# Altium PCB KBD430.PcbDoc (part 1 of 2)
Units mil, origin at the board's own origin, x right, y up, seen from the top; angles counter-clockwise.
Board outline 5000 x 5500 mil, 4 copper layers (Top Layer, Ground Plane, Power Plane, Bottom Layer), stack 90 mil thick; 72 components, 94 nets, 353 pads, 293 vias.
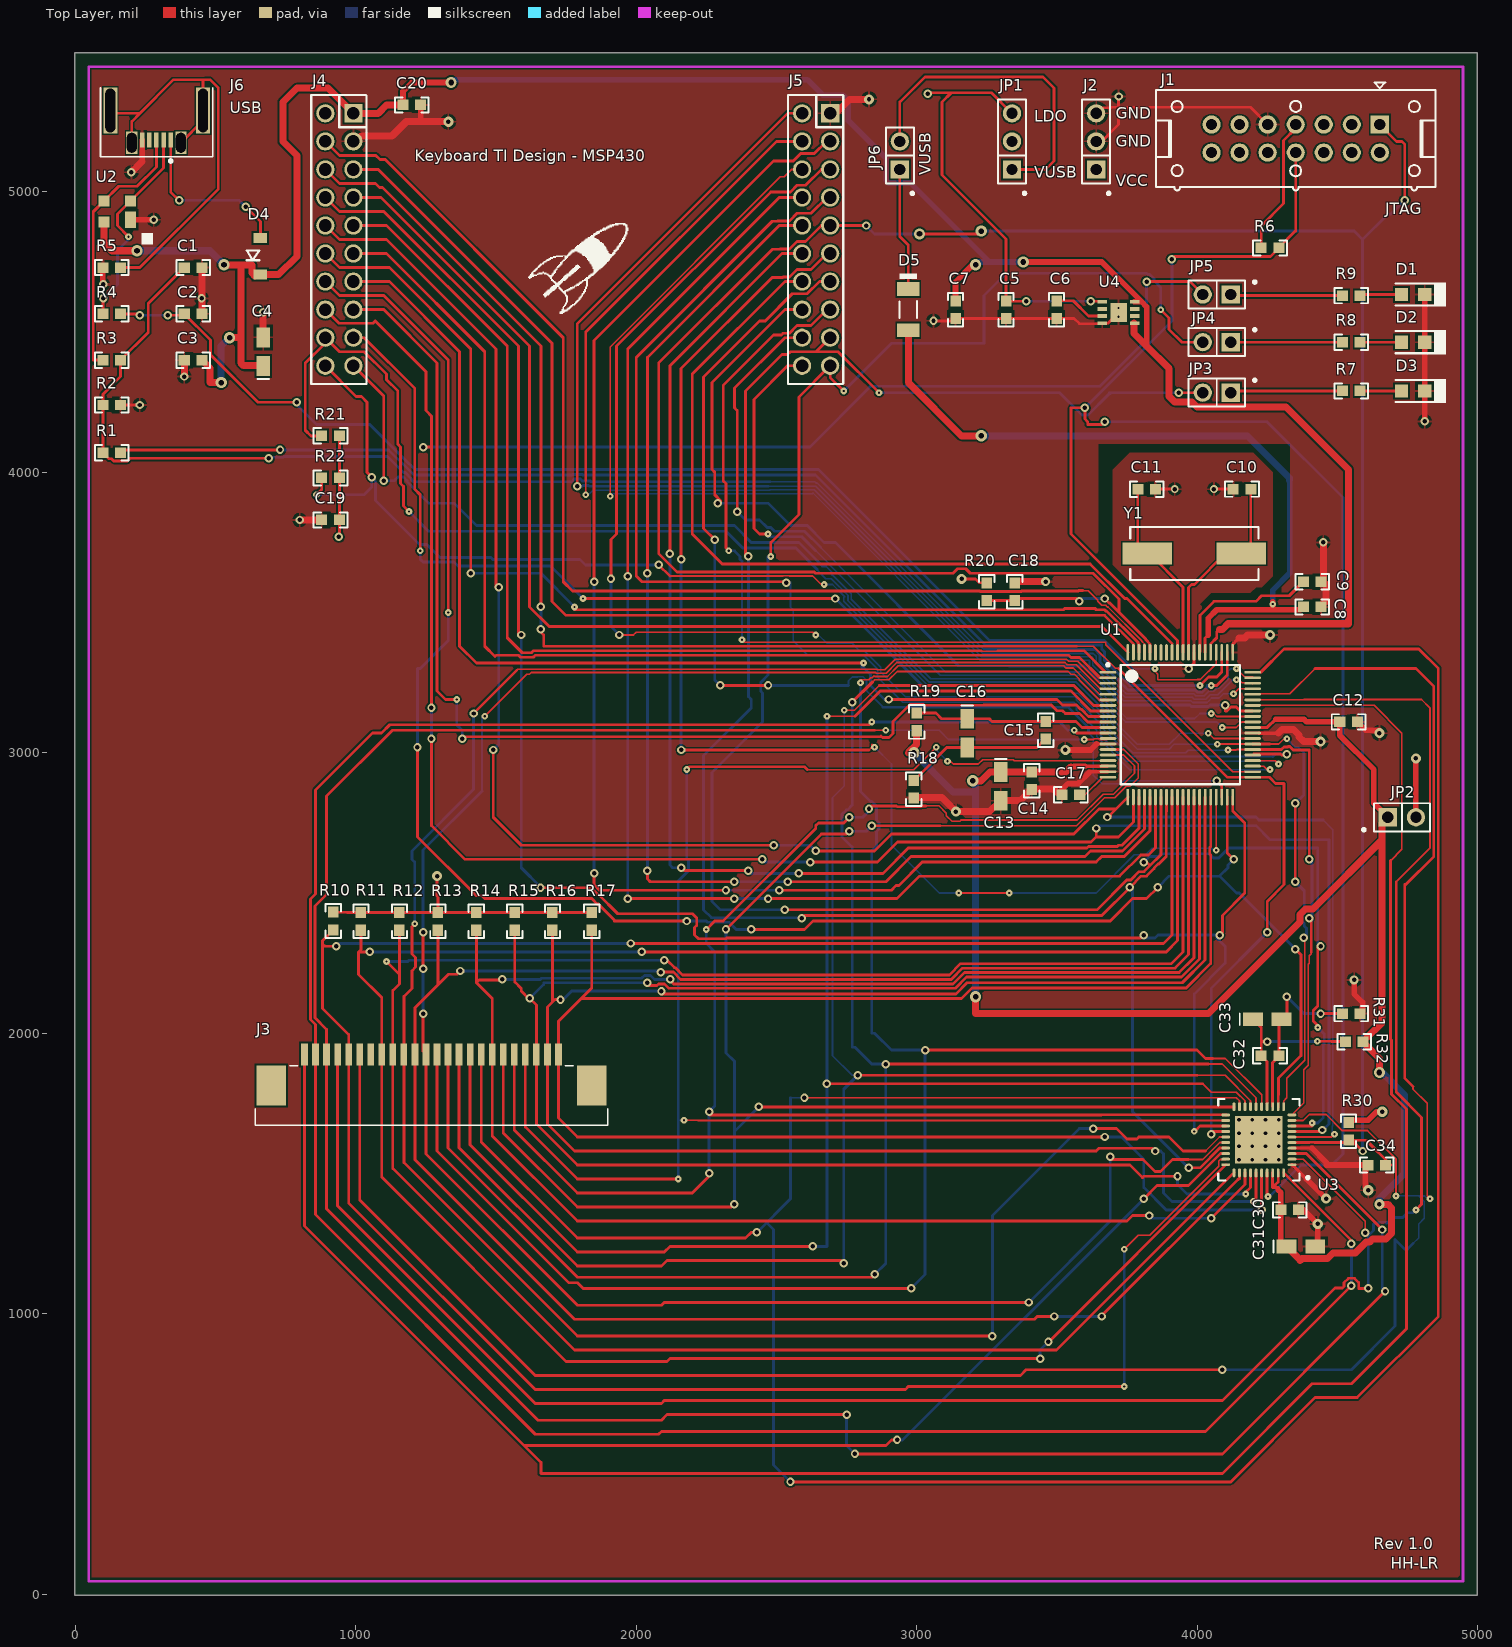
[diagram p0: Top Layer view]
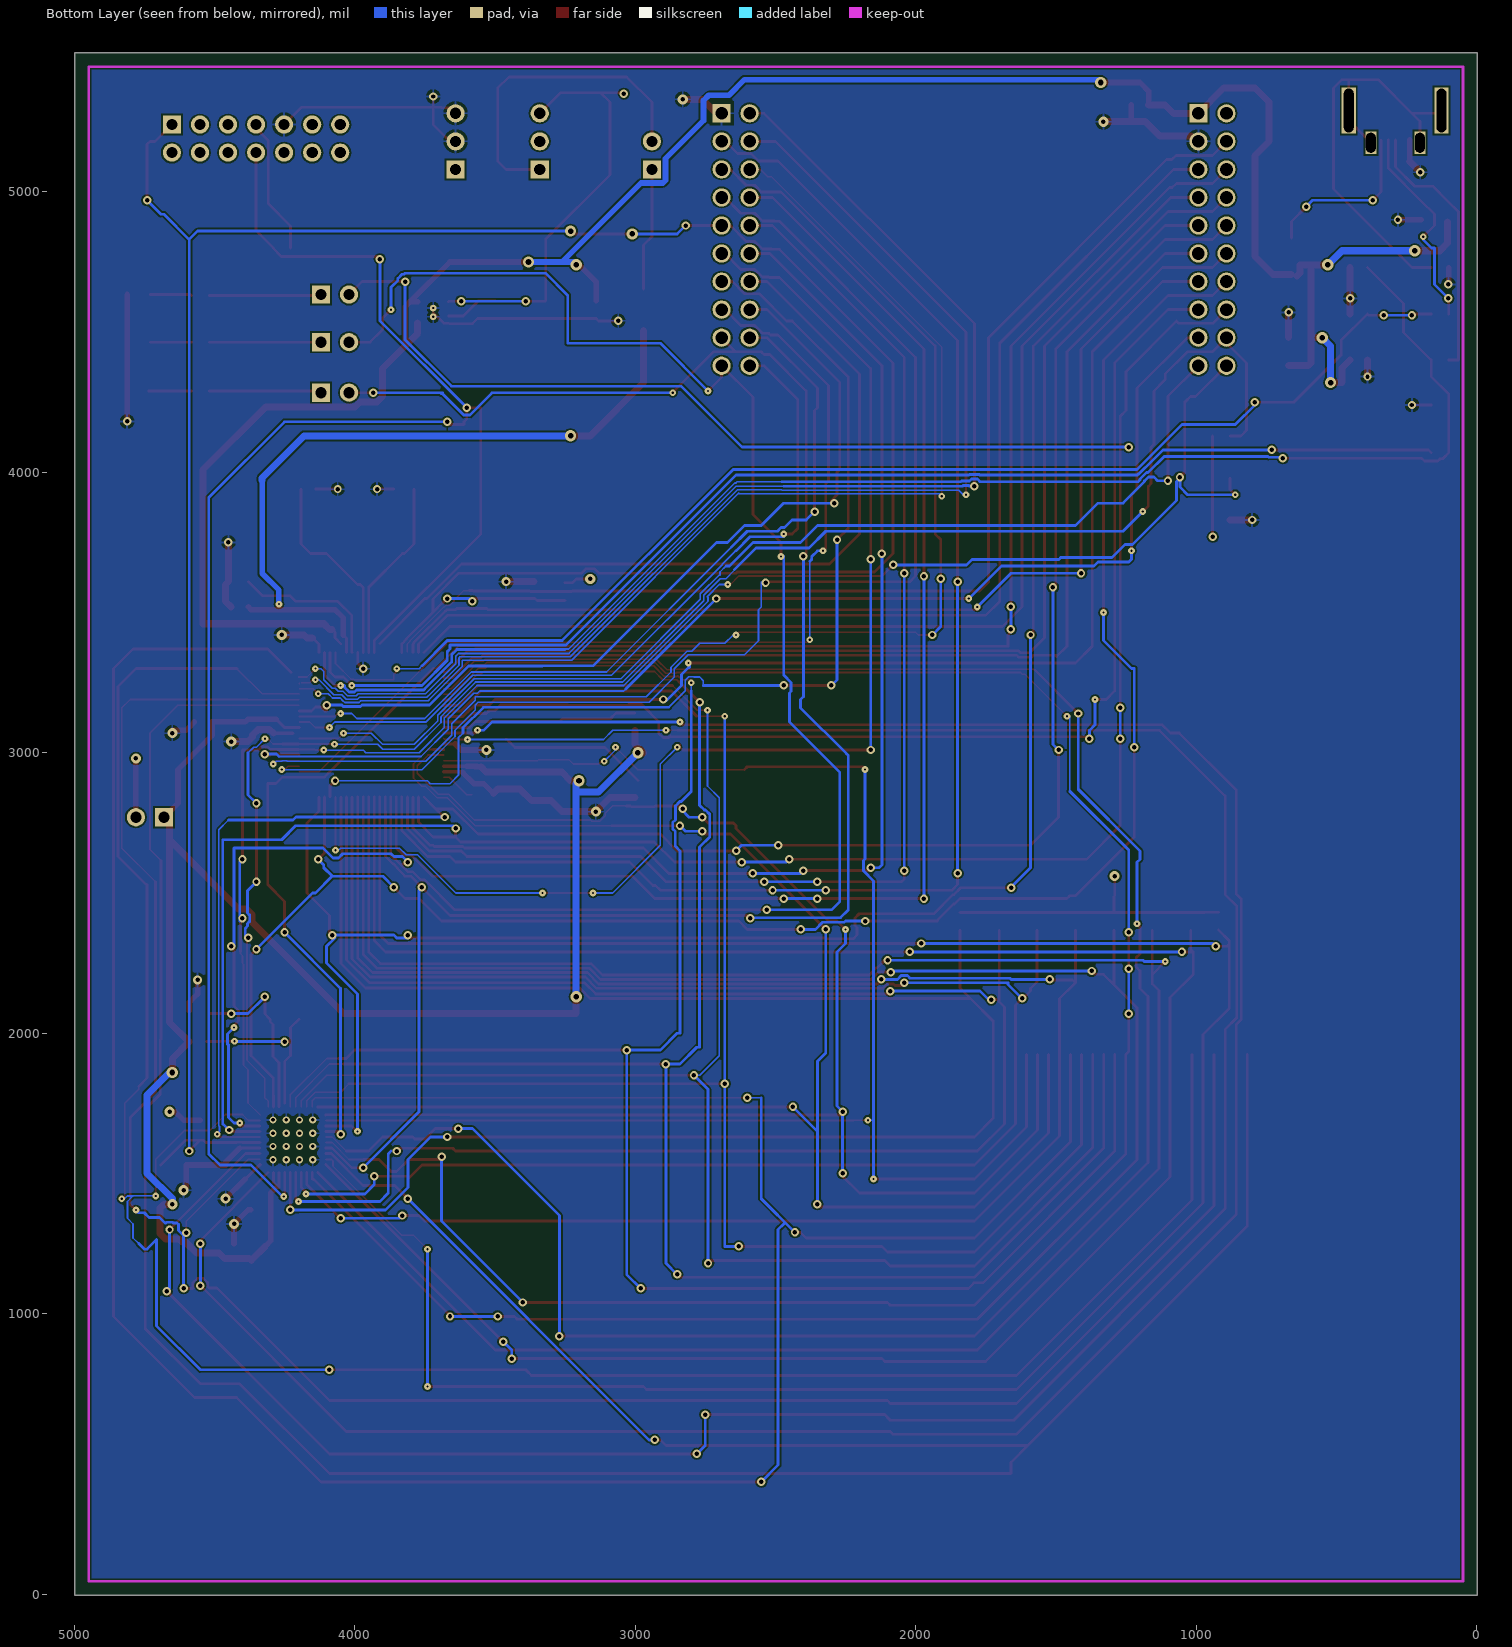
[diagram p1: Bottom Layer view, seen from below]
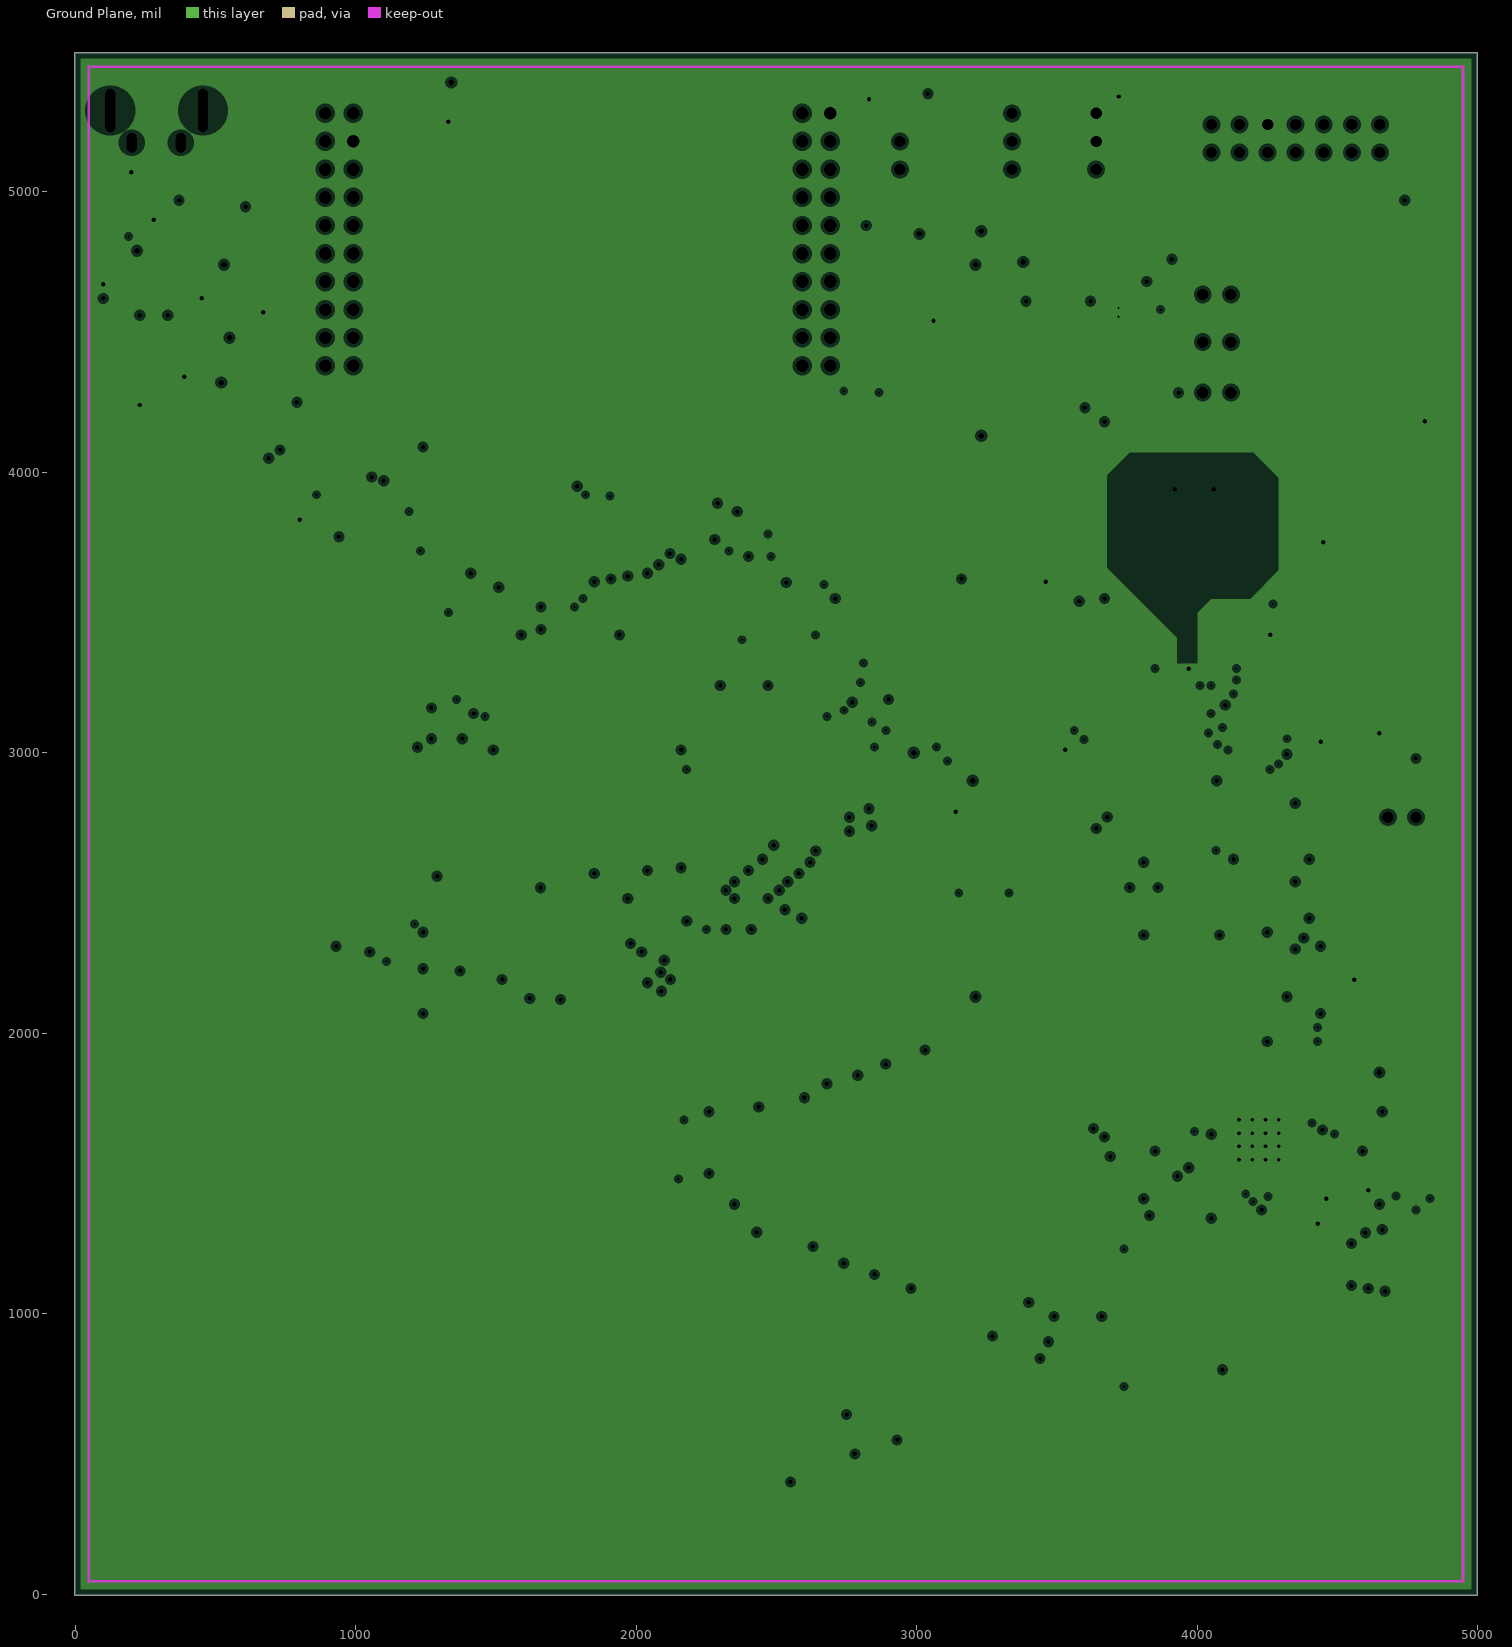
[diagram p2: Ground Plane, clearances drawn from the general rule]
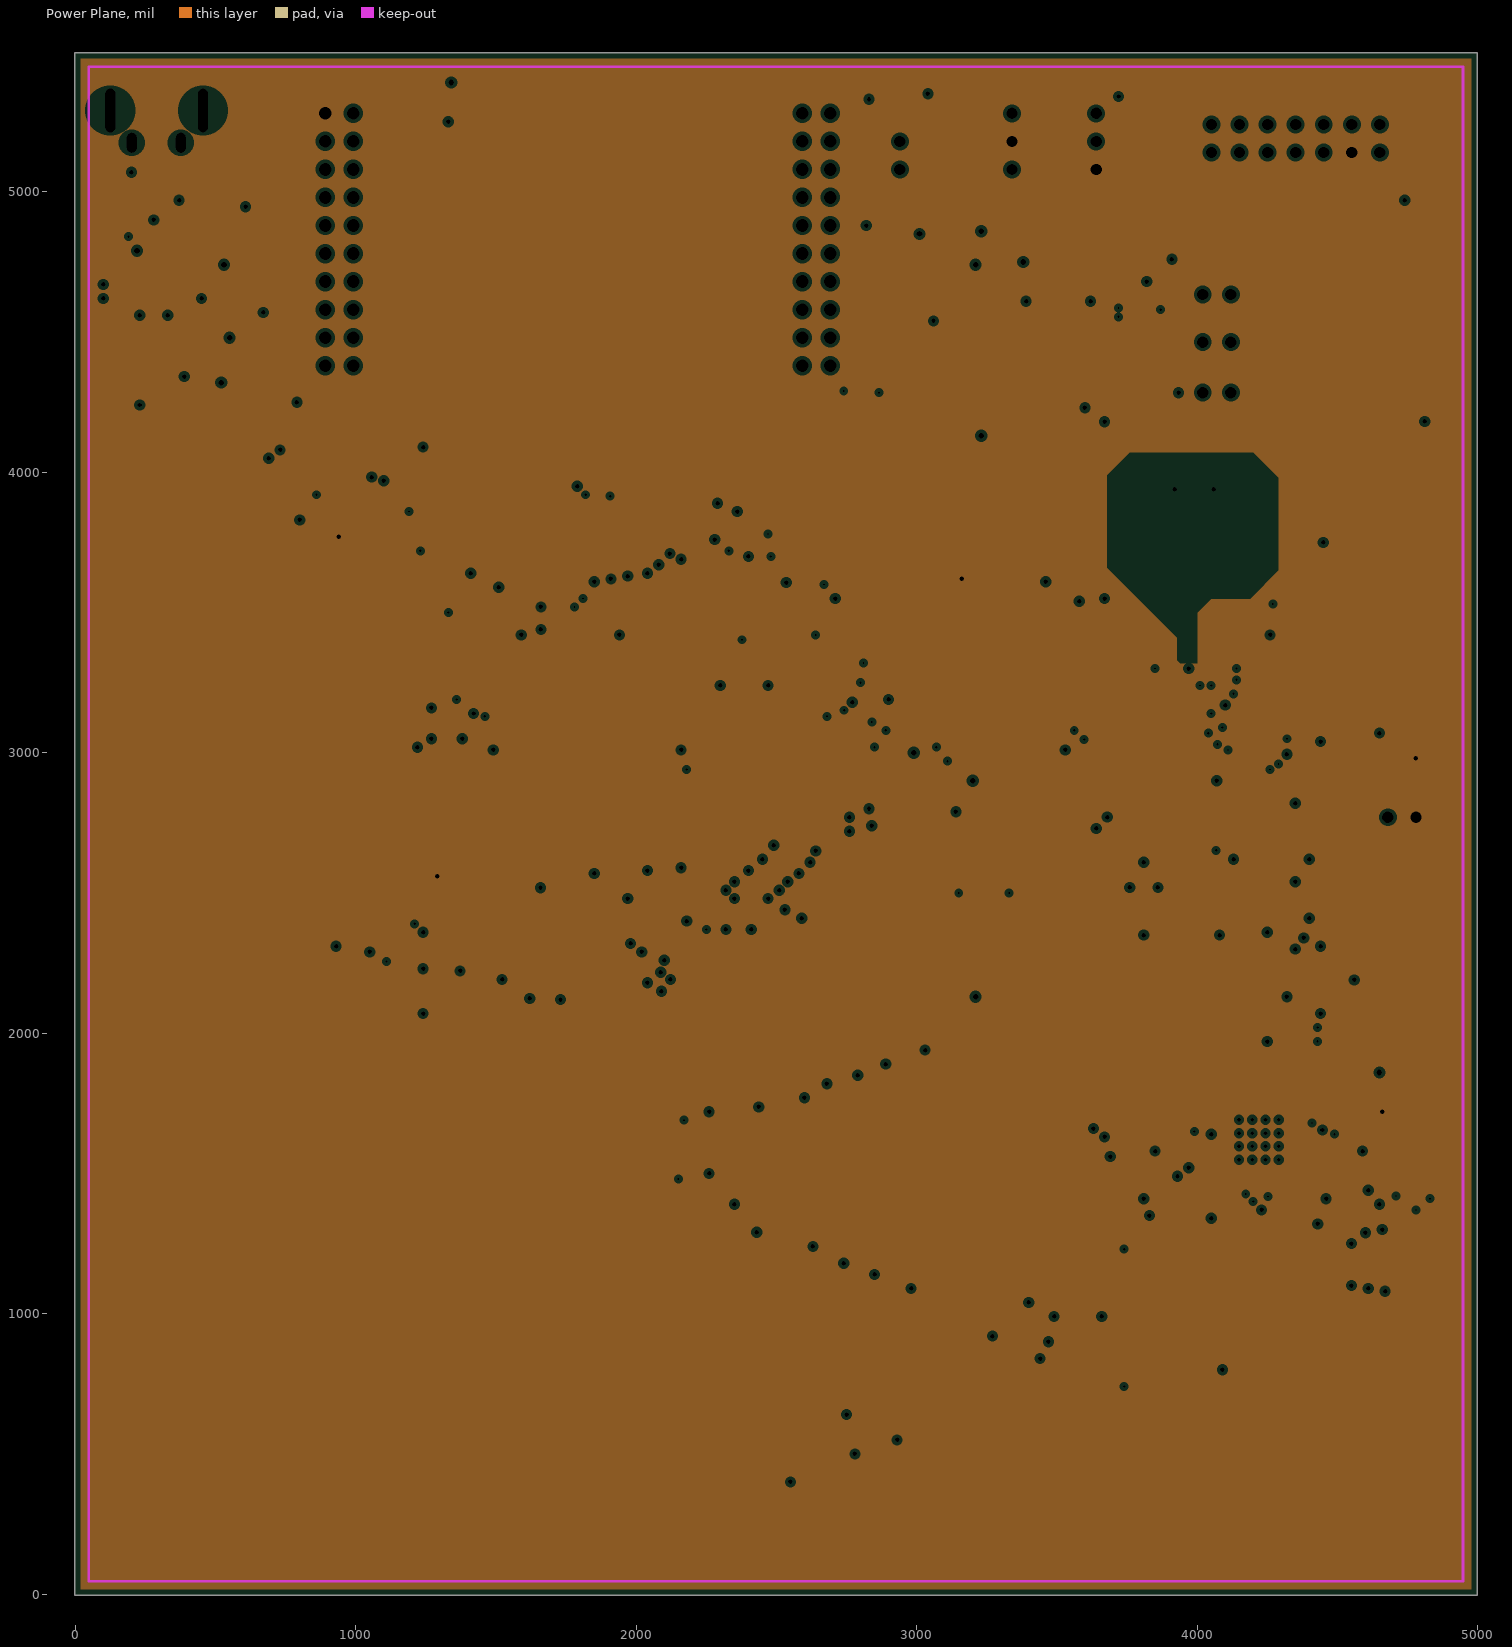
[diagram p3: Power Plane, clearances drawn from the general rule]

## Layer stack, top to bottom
Top Layer: signal copper 1.4
Dielectric: core 59.2, FR-4, Dk 4.8
Ground Plane: plane copper 1.4, net GND
Dielectric: prepreg 12.6, FR-4, Dk 4.8
Power Plane: plane copper 1.4, net VCC
Dielectric: core 12.6, FR-4, Dk 4.8
Bottom Layer: signal copper 1.4

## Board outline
-2,-4 4998,-4 4998,5496 -2,5496

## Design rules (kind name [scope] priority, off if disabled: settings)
Clearance "Clearance~Sunstone Circuits" [All] p1: gap=6 // Sunstone Circuits Minimum Clearance Rule (MLB~4&6 Layer Designs)
FanoutControl Fanout_BGA [InComponent('U3')] p1: bgadir=Out bgaviamode=Centered fanoutstyle=Auto fanoutdirection=Alternating viagrid=1 // Fanout_BGA (Default Rule)
HoleSize "HoleSize~Sunstone Circuits" [All] p1: absolutevalues=TRUE maxlimit=251 minlimit=8 maxpercent=80.000 minpercent=20.000 // Sunstone Circuits Hole Size Rule (MLB~4&6 Layer Designs)
HoleSize Testpoint [All] p2: absolutevalues=TRUE maxlimit=100 minlimit=1 maxpercent=80.000 minpercent=20.000
HoleSize TestPointUsage [All] p3: absolutevalues=TRUE maxlimit=100 minlimit=1 maxpercent=80.000 minpercent=20.000
MinimumAnnularRing "MinimumAnnularRing~Sunstone Circuits" [All] p1: minimumring=2 // Sunstone Circuits Minimum Annular Ring (MLB~4&6 Layer Designs)
MinimumSolderMaskSliver [All] p1: minsoldermaskwidth=2.5
PlaneClearance "PlaneClearance~Sunstone Circuits" [All] p1: clearance=12 // Sunstone Circuits Power Plane Clearance Rule (MLB~4&6 Layer Designs)
PlaneConnect "PlaneConnect~Sunstone Circuits" [All] p1: planeconnectstyle=Relief reliefexpansion=10 reliefentries=4 reliefconductorwidth=8 reliefairgap=10 // Sunstone Circuits Power Plane Connect Rule (MLB~4&6 Layer Designs)
PolygonConnect "PolygonConnect~Sunstone Circuits" [All] p1: connectstyle=Relief reliefconductorwidth=8 reliefentries=4 polygonreliefangle="90 Angle" airgapwidth=10 // Sunstone Circuits Polygon Connect Style (MLB~4&6 Layer Designs)
RoomDefinition KBD430_Shared [InComponentClass('KBD430_Shared')] p1: confinementstyle=ConfineIn formatcopy=TRUE lockcomponents=FALSE outline 10,5520 40,5490 4980,5490 4980,10 4990,0 0,0 0,4700 10,4710
RoomDefinition KBD430_G2xx4 [InComponentClass('KBD430_G2xx4')] p2: confinementstyle=ConfineIn formatcopy=TRUE lockcomponents=FALSE outline 0,5520 4970,5520 5010,5480 5010,-20 40,-20 0,20 0,180 -10,190
RoomDefinition KBD430_F5529 [InComponentClass('KBD430_F5529')] p3: confinementstyle=ConfineIn formatcopy=TRUE lockcomponents=FALSE outline -10,5520 4990,5520 5000,5510 5000,-30 30,-30 -10,10
RoutingVias "RoutingVias~Sunstone Circuits" [All] p1: holewidth=16 width=30 viastyle="Through Hole" minholewidth=8 minwidth=24 maxholewidth=20 maxwidth=40 // Sunstone Circuits Routing Vias Rule (MLB~4&6 Layer Designs)
ShortCircuit "ShortCircuit~Sunstone Circuits" [All] p1: allowed=FALSE // Sunstone Circuits Short Circuit Rule~Do Not Allow (MLB~4&6 Layer Designs)
SilkToSilkClearance [All] p1: silktosilkclearance=6
SilkscreenOverComponentPads [All] p1: minsilkscreentomaskgap=4
SolderMaskExpansion "SolderMaskExpansion~Sunstone Circuits" [All] p1: expansion=3 // Sunstone Circuits Solder Mask Expansion Rule (MLB~4&6 Layer Designs)
ViasUnderSMD "ViasUnderSMD~Sunstone Circuits" [All] p1: allowed=TRUE // Sunstone Circuits Vias Under SMD~Do Not Allow (MLB~4&6 Layer Designs)
Width "Width~Sunstone Circuits" [All] p1: maxlimit=100 minlimit=6 preferedwidth=10 // Sunstone Circuits Minimum Width Rule (MLB~4&6 Layer Designs)
20 further rules are at their usual default settings.

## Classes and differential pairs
component class Header: J2 JP1 JP2 JP3 JP4 JP5 JP6
component class KBD430_F5529: C1 C2 C3 C4 C8 C9 C10 C11 C12 C13 C14 C15 C16 C17 C18 D4 D5 J6 JP6 R1 R2 R3 R4 R5 R18 R19 R20 U1 U2 Y1
component class KBD430_G2xx4: C30 C31 C32 C33 C34 R30 R31 R32 U3
component class KBD430_Shared: C5 C6 C7 C19 C20 D1 D2 D3 J1 J2 J3 J4 J5 JP1 JP2 JP3 JP4 JP5 LED1 LED2 R6 R7 R8 R9 R10 R11 R12 R13 R14 R15 R16 R17 R21 R22 U4

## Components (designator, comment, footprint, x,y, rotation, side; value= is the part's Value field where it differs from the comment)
C1 "10pF" 0603 420,4730 r0 top
C2 "10pF" 0603 420,4564.97 r0 top
C3 "0.1uF" 0603 420,4400 r180 top
C4 "4.7µF" 3216-18 670,4430 r90 top
C5 "4.7uF" 0603 3318.59,4580 r270 top
C6 "0.01uF" 0603 3498.72,4580 r90 top
C7 "1uF" 0603 3138.46,4580 r270 top
C8 "0.22uF" 0603 4410,3520 r0 top
C9 "0.22uF" 0603 4410,3610 r0 top
C10 "33pF" 0603 4160,3940 r0 top
C11 "33pF" 0603 3820,3940 r180 top
C12 "0.1uF" 0603 4540,3110 r0 top
C13 "10uF" 3216-18 3300,2880 r270 top
C14 "0.1uF" 0603 3410,2900 r270 top
C15 "0.1uF" 0603 3460,3080 r270 top
C16 "10uF" 3216-18 3180,3070 r270 top
C17 "0.47uF" 0603 3550,2850 r180 top
C18 "DNP" 0603 3350,3574.45 r90 top
C19 "0.1uF" 0603 910,3830 r0 top
C20 "0.1uF" 0603 1200,5310 r180 top
C30 "DNP" 0603 4330,1370 r0 top
C31 "DNP" 3216-18 4370,1240 r0 top
C32 "DNP" 0603 4260,1920 r0 top
C33 "DNP" 3216-18 4250,2050 r0 top
C34 "DNP" 0603 4640,1530 r180 top
D1 "LTST-C171GKT" LED_LTST-C171 4770,4634 r0 top
D2 "LTST-C171GKT" LED_LTST-C171 4770,4464 r0 top
D3 "LTST-C171GKT" LED_LTST-C171 4770,4290 r0 top
D4 "SD103AW-13-F" D_SOD123 660,4770 r270 top
D5 "LL103A-GS08" SOD-80 2970,4580 r270 top
J1 "SBH11-PBPC-D07-ST-BK" CONN_SBH11-PBPC-D07-ST-BK 4351.5,5190 r180 top
J2 "TSW-103-07-G-S" TSW-103-07-G-S 3640,5180 r90 top
J3 "2-84952-4" CON24_SMT-RA_FCC 1270,2070 r180 top
J4 "SSW-110-23-F-D" CONN_SSW-110-23-F-D 991.5,5280 r90 top
J5 "SSW-110-23-F-D" CONN_SSW-110-23-F-D 2691.5,5280 r90 top
J6 "ZX62D-AB-5P8" USB-ZX62D-AB-5P8_REVISED 290,5290 r270 top
JP1 "TSW-103-07-G-S" TSW-103-07-G-S 3340,5180 r90 top
JP2 "TSW-102-07-G-S" TSW-102-07-G-S 4730,2770 r0 top
JP3 "TSW-102-07-G-S" TSW-102-07-G-S 4070,4284 r180 top
JP4 "TSW-102-07-G-S" TSW-102-07-G-S 4070,4464 r180 top
JP5 "TSW-102-07-G-S" TSW-102-07-G-S 4070,4634 r180 top
JP6 "TSW-102-07-G-S" TSW-102-07-G-S 2940,5130 r90 top
R1 "1.40k" 0603 130,4070 r180 top
R2 "1.0Meg" 0603 130,4240 r180 top
R3 "27" 0603 130,4400 r180 top
R4 "27" 0603 130,4565 r180 top
R5 "33k" 0603 130,4730 r0 top
R6 "330" 0603 4260,4800 r0 top
R7 "560" 0603 4550,4290 r180 top
R8 "560" 0603 4550,4464 r180 top
R9 "560" 0603 4550,4630 r180 top
R10 "47k" 0603 920,2400 r90 top
R11 "47k" 0603 1018.57,2398.7 r90 top
R12 "47k" 0603 1155.71,2398.7 r90 top
R13 "47k" 0603 1292.86,2398.7 r90 top
R14 "47k" 0603 1430,2398.7 r90 top
R15 "47k" 0603 1567.14,2398.7 r90 top
R16 "47k" 0603 1701.3,2398.7 r90 top
R17 "47k" 0603 1841.43,2398.7 r90 top
R18 "0" 0603 2990,2870 r90 top
R19 "0" 0603 3000,3110 r90 top
R20 "47k" 0603 3250,3574.45 r90 top
R21 "2.2k" 0603 910,4130 r180 top
R22 "2.2k" 0603 910,3980 r180 top
R30 "DNP" 0603 4540,1650 r90 top
R31 "DNP" 0603 4550,2070 r180 top
R32 "DNP" 0603 4560,1970 r180 top
U1 "MSP430F5529IPN" PN0080A_L 3940,3100 r0 top
U2 "TPD2E001DZDR" DZD 150,4930 r90 top
U3 "DNP" QFN50P600X600X100-40N 4220,1620 r180 top
U4 "TPS73533DRBT" DRB8_1P75X1P5 3720,4570 r0 top
Y1 "HC49US-4.000MABJB" Auris_HC49USSMD 3990,3710 r180 top

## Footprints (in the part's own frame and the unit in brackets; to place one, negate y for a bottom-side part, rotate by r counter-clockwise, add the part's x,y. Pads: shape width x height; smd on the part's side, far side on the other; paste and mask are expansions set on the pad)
0603 [mm] "0603 from SM-752 data"
  rect 1x0.95 smd: 1(-0.8,0) 2(0.8,0)
  silkscreen extent -1.52,-0.69 1.52,0.69, body extent -0.87,-0.47 0.87,0.47, height 0.85
3216-18 [mm] "Medium density IPC, based on Kemet T495 dimensions"
  rect 1.8x1.25 smd: 1(-1.3,0) 2(1.3,0)
  silkscreen extent -2.49,-0.54 -2.49,0.54, body extent -1.7,-0.9 1.7,0.9, height 1.8
Auris_HC49USSMD [mm] "Auris"
  rect 4.5x2 smd: 1(-4.25,0) 2(4.25,0)
  silkscreen extent -5.8,-2.4 5.8,2.4, body extent -5.8,-2.41 5.8,2.41, height 4.5
CON24_SMT-RA_FCC [mil]
  rect 24x79 smd: 1(452.76,146) 2(413.39,146) 3(374.02,146) 4(334.65,146) 5(295.28,146) 6(255.91,146) 7(216.54,146) 8(177.17,146) 9(137.8,146) 10(98.43,146) 11(59.06,146) 12(19.68,146) 13(-19.69,146) 14(-59.06,146) 15(-98.43,146) 16(-137.8,146) 17(-177.17,146) 18(-216.54,146) 19(-255.91,146) 20(-295.28,146) 21(-334.65,146) 22(-374.02,146) 23(-413.39,146) 24(-452.76,146)
  rect 105x142 smd: 25(-571.5,256.5) 26(571.5,256.5)
  silkscreen extent -628,185 628,399
CONN_SBH11-PBPC-D07-ST-BK [mm] "Sullins recommended land pattern"
  rect 1.65x1.65 hole 1.016 mask+0: 1(-7.62,-1.27)
  round 1.65 hole 1.016 mask+0: 2(-7.62,1.27) 3(-5.08,-1.27) 4(-5.08,1.27) 5(-2.54,-1.27) 6(-2.54,1.27) 7(0,-1.27) 8(0,1.27) 9(2.54,-1.27) 10(2.54,1.27) 11(5.08,-1.27) 12(5.08,1.27) 13(7.62,-1.27) 14(7.62,1.27)
  silkscreen extent -12.64,-5.08 12.64,4.7, body extent -12.64,-4.4 12.64,4.7, height 9.12
CONN_SSW-110-23-F-D [mm] "SAMTEC"
  rect 1.65x1.65 hole 1.15: 1(0,0)
  round 1.65 hole 1.15: 2(0,2.54) 3(-2.54,0) 4(-2.54,2.54) 5(-5.08,0) 6(-5.08,2.54) 7(-7.62,0) 8(-7.62,2.54) 9(-10.16,0) 10(-10.16,2.54) 11(-12.7,0) 12(-12.7,2.54) 13(-15.24,0) 14(-15.24,2.54) 15(-17.78,0) 16(-17.78,2.54) 17(-20.32,0) 18(-20.32,2.54) 19(-22.86,0) 20(-22.86,2.54)
  silkscreen extent -24.51,-1.19 1.65,3.81, body extent -24.43,-1.24 1.57,3.81, height 8.59
D_SOD123 [mil]
  rect 36x48 smd: 1(65,0) 2(-65,0)
  silkscreen extent -21,-49 14,-3
DRB8_1P75X1P5 [mm]
  rect 0.85x0.35 smd paste-0.412: 1(-1.475,0.975) 2(-1.475,0.325) 3(-1.475,-0.325) 4(-1.475,-0.975) 5(1.475,-0.975) 6(1.475,-0.325) 7(1.475,0.325) 8(1.475,0.975)
  rect 1.5x1.75 smd paste-0.862 mask-0.864: 9(0,0)
  round 0.61 hole 0.203: V(0,-0.394) V_2(0,0.394)
DZD [mm]
  rect 1.5x1 smd: 1(-0.76,-1.2)
  rect 1x1 smd mask+0.05: 2(0.96,-1.2) 3(0.96,1.2) 4(-0.96,1.2)
  silkscreen extent -2.99,-3.21 -1.97,-2.19
LED_LTST-C171 [mm] "LITE-ON"
  rect 1.2x1.2 smd: 1(-1.05,0) 2(1.05,0)
  silkscreen extent -1.6,-1.1 3,1.1, body extent -1.05,-0.67 1.05,0.67, height 0.8
PN0080A_L [mm] "QFP, 80-Leads, Body 12x12mm, Pitch 0.5mm, IPC High Density"
  oval 1.5x0.25 smd: 1(-6.55,4.75) 2(-6.55,4.25) 3(-6.55,3.75) 4(-6.55,3.25) 5(-6.55,2.75) 6(-6.55,2.25) 7(-6.55,1.75) 8(-6.55,1.25) 9(-6.55,0.75) 10(-6.55,0.25) 11(-6.55,-0.25) 12(-6.55,-0.75) 13(-6.55,-1.25) 14(-6.55,-1.75) 15(-6.55,-2.25) 16(-6.55,-2.75) 17(-6.55,-3.25) 18(-6.55,-3.75) 19(-6.55,-4.25) 20(-6.55,-4.75) 41(6.55,-4.75) 42(6.55,-4.25) 43(6.55,-3.75) 44(6.55,-3.25) 45(6.55,-2.75) 46(6.55,-2.25) 47(6.55,-1.75) 48(6.55,-1.25) 49(6.55,-0.75) 50(6.55,-0.25) 51(6.55,0.25) 52(6.55,0.75) 53(6.55,1.25) 54(6.55,1.75) 55(6.55,2.25) 56(6.55,2.75) 57(6.55,3.25) 58(6.55,3.75) 59(6.55,4.25) 60(6.55,4.75)
  oval 0.25x1.5 smd: 21(-4.75,-6.55) 22(-4.25,-6.55) 23(-3.75,-6.55) 24(-3.25,-6.55) 25(-2.75,-6.55) 26(-2.25,-6.55) 27(-1.75,-6.55) 28(-1.25,-6.55) 29(-0.75,-6.55) 30(-0.25,-6.55) 31(0.25,-6.55) 32(0.75,-6.55) 33(1.25,-6.55) 34(1.75,-6.55) 35(2.25,-6.55) 36(2.75,-6.55) 37(3.25,-6.55) 38(3.75,-6.55) 39(4.25,-6.55) 40(4.75,-6.55) 61(4.75,6.55) 62(4.25,6.55) 63(3.75,6.55) 64(3.25,6.55) 65(2.75,6.55) 66(2.25,6.55) 67(1.75,6.55) 68(1.25,6.55) 69(0.75,6.55) 70(0.25,6.55) 71(-0.25,6.55) 72(-0.75,6.55) 73(-1.25,6.55) 74(-1.75,6.55) 75(-2.25,6.55) 76(-2.75,6.55) 77(-3.25,6.55) 78(-3.75,6.55) 79(-4.25,6.55) 80(-4.75,6.55)
  silkscreen extent -6.67,-5.4 5.4,5.55, body extent -7,-7 7,7, height 1.52
QFN50P600X600X100-40N [mm] "QFN, 40-Leads, Body 6.2x6.2mm (max), Pitch 0.50mm, IPC Medium Density"
  oval 0.8x0.25 smd: 1(-3,2.25) 2(-3,1.75) 3(-3,1.25) 4(-3,0.75) 5(-3,0.25) 6(-3,-0.25) 7(-3,-0.75) 8(-3,-1.25) 9(-3,-1.75) 10(-3,-2.25) 21(3,-2.25) 22(3,-1.75) 23(3,-1.25) 24(3,-0.75) 25(3,-0.25) 26(3,0.25) 27(3,0.75) 28(3,1.25) 29(3,1.75) 30(3,2.25)
  oval 0.25x0.8 smd: 11(-2.25,-3) 12(-1.75,-3) 13(-1.25,-3) 14(-0.75,-3) 15(-0.25,-3) 16(0.25,-3) 17(0.75,-3) 18(1.25,-3) 19(1.75,-3) 20(2.25,-3) 31(2.25,3) 32(1.75,3) 33(1.25,3) 34(0.75,3) 35(0.25,3) 36(-0.25,3) 37(-0.75,3) 38(-1.25,3) 39(-1.75,3) 40(-2.25,3)
  rect 4.3x4.3 smd: 41(0,0)
  silkscreen extent -4.57,-3.68 3.68,3.68, body extent -3.08,-3.08 3.08,3.08, height 1
SOD-80 [mm] "VISHAY"
  rect 1.25x2 smd: 1(-1.875,0) 2(1.875,0)
  silkscreen extent -3.29,-0.8 0.76,0.8, body extent -1.85,-0.81 1.85,0.81, height 1.62
TSW-102-07-G-S [mm] "Samtec 100mil, 1x2, 230 mil above insulator"
  rect 1.65x1.65 hole 1.016 mask+0: 1(-1.27,0)
  round 1.65 hole 1.016 mask+0: 2(1.27,0)
  silkscreen extent -3.56,-1.27 2.54,1.27, body extent -2.54,-1.27 2.54,1.27, height 8.38
TSW-103-07-G-S [mm] "Samtec 100mil, 1x3, 230 mil above insulator"
  rect 1.65x1.65 hole 1.016 mask+0: 1(-2.54,0)
  round 1.65 hole 1.016 mask+0: 2(0,0) 3(2.54,0)
  silkscreen extent -4.83,-1.27 3.81,1.27, body extent -3.81,-1.27 3.81,1.27, height 8.38
USB-ZX62D-AB-5P8_REVISED [mil]
  rect 53x16 smd: 1(105,50) 2(105,24.5) 3(105,-1) 4(105,-26.5) 5(105,-52)
  rect 80x40 hole 35 slot 70 at 0 deg: 6(115,-88.5) 7(115,86.5)
  rect 165x50 hole 35 slot 155 at 0 deg: 8(0,-165.35) 9(0,165.35)
  silkscreen extent -80,-200 185,200

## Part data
C1 C2: library part C0603C100J5GACTU, "CAP, CERM, 10pF, 50V, +/-5%, C0G/NP0, 0603"
C3: library part C0603C104K5RACTU, "CAP, CERM, 0.1uF, 50V, +/-10%, X7R, 0603"
C4: library part 293D475X9010A2TE3, "CAP, TA, 4.7uF, 10V, +/-10%, 5 ohm, SMD"
C5: library part C0603C475K8PACTU, "CAP, CERM, 4.7uF, 10V, +/-10%, X5R, 0603"
C6: library part GRM188R71H103KA01D, "CAP, CERM, 0.01uF, 50V, +/-10%, X7R, 0603"
C7: library part C0603C105K4PACTU, "CAP, CERM, 1uF, 16V, +/-10%, X5R, 0603"
C8 C9: library part C1608X7R1C224K, "CAP, CERM, 0.22uF, 16V, +/-10%, X7R, 0603"
C10 C11: library part C1608C0G1H330J, "CAP, CERM, 33pF, 50V, +/-5%, C0G/NP0, 0603"
C12 C14 C15 C30 C32: library part C0603C104K4RACTU, "CAP, CERM, 0.1uF, 16V, +/-10%, X7R, 0603"
C13 C16 C31 C33: library part 293D106X0010A2TE3, "CAP, TA, 10uF, 10V, +/-20%, 3.4 ohm, SMD"
C17: library part C0603C474K8PACTU, "CAP, CERM, 0.47uF, 10V, +/-10%, X5R, 0603"
C18 C34: library part 06031C222JAT2A, "CAP, CERM, 2200pF, 100V, +/-5%, X7R, 0603"
C19 C20: library part 0603YC104JAT2A, "CAP, CERM, 0.1uF, 16V, +/-5%, X7R, 0603"
D1 D2 D3: "LED, Green, SMD"
D4: "DIODE, SCHOTTKY, 0.35A, 40V, SOD-123"
D5: "Diode, Schottky, 40V, 0.2A, 3.7x1.6x1.6mm"
J1: "Header (shrouded), 100 mil, 7x2, Gold, TH"
J2 JP1: "Header, 100mil, 3x1, Gold, TH"
J3: "CONN FPC 24POS 1MM RT ANG SMD"
J4 J5: "Connector, Receptacle, 100mil, 10x2, Gold plated, TH"
J6: "CONNECTOR,  MICRO-USB-AB, RECEPTACLE, RIGHT ANGLE, 5-PIN"
JP2 JP3 JP4 JP5 JP6: "Header, 100mil, 2x1, Gold, TH"
R1: library part CRCW06031K40FKEA, "RES, 1.40k ohm, 1%, 0.1W, 0603"
R2: library part CRCW06031M00JNEA, "RES, 1.0Meg ohm, 5%, 0.1W, 0603"
R3 R4: library part CRCW060327R0JNEA, "RES, 27 ohm, 5%, 0.1W, 0603"
R5: library part CRCW060333K0JNEA, "RES, 33k ohm, 5%, 0.1W, 0603"
R6: library part CRCW0603330RJNEA, "RES, 330 ohm, 5%, 0.1W, 0603"
R7 R8 R9: library part CRCW0603560RJNEA, "RES, 560 ohm, 5%, 0.1W, 0603"
R10 R11 R12 R13 R14 R15 R16 R17 R20 R30: library part CRCW060347K0JNEA, "RES, 47k ohm, 5%, 0.1W, 0603"
R18 R19 R31 R32: library part CRCW06030000Z0EA, "RES, 0 ohm, 5%, 0.1W, 0603"
R21 R22: library part CRCW06032K20JNEA, "RES, 2.2k ohm, 5%, 0.1W, 0603"
U1: "Mixed Signal MicroController, PN0080A"
U2: "IC, LOW-CAPACITANCE 2-Chan ±15-kV ESD-PROTECTION ARRAY, SOP-4"
U3: library part MSP430G2744_RHA_, "MSP430G2744, VQFN40"
U4: "Single Output High PSRR LDO, 500 mA, Fixed 3.3 V Output, 2.7 to 6.5 V Input, with Low IQ, 8-pin SON (DRB), -40 to 125 degC, Green (RoHS & no Sb/Br)"
Y1: library part Q-4M-HC49USSMD-F-30-50-E-30-TR, "Crystal, 4MHz, 30pF, SMD"

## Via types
v1: diameter 30, hole 16, Top Layer to Bottom Layer, 176 vias
v2: diameter 24, hole 8, Top Layer to Bottom Layer, 68 vias
v3: diameter 25.98, hole 12.99, Top Layer to Bottom Layer, tented top, 16 vias
v4: diameter 40, hole 20, Top Layer to Bottom Layer, 14 vias
v5: diameter 36, hole 16, Top Layer to Bottom Layer, 13 vias
v6: diameter 32, hole 16, Top Layer to Bottom Layer, 2 vias
v7: diameter 28, hole 16, Top Layer to Bottom Layer, 2 vias
v8: diameter 36, hole 16, Top Layer to Bottom Layer, tented top, 1 vias
v9: diameter 36, hole 16, Top Layer to Bottom Layer, tented both sides, 1 vias

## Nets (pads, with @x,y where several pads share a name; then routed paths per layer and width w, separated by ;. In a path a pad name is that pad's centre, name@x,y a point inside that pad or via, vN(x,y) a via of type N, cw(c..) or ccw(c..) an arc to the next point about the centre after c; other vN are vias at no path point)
AIN1: J4.4 U1.77 | length 4208.6
  Top Layer w6: 3591.86,3578.06 3611.94,3578.06 3646,3544 3646,3540.06 3660.06,3526 3674,3526 3680,3520 3682.43,3520 3802.68,3399.75 3802.68,3397.32 3812.05,3387.95 U1.77@3812.05,3357.87
  Top Layer w10: J4.4@891.5,5180 941.5,5130 1071.36,5130 1086.36,5115 1105,5115 1740,4480 1740,3610 1773,3577 3225,3577 3226.74,3575.26 3373.26,3575.26 3375,3577 3577,3577 3578.06,3578.06 3591.86,3578.06
AIN2: J4.12 U1.78 | length 3987.6
  Top Layer w10: J4.12@891.5,4780 941.5,4730 1120,4730 1410,4440 v1(1410,3640) ; v2(1780,3520) 1780,3510 3524,3510 3528,3514 3634.1,3514 3635.17,3515.07 3640.24,3510 3670.2,3510 3674.2,3506 3676.63,3506 3788.68,3393.95 3788.68,3391.52 3792.36,3387.84 U1.78@3792.36,3357.87
  Bottom Layer w10: v1(1410,3640) 1660,3640 v2(1780,3520)
AIN3: J4.5 U1.79 | length 4050.7
  Top Layer w10: J4.5@991.5,5080 1080,5080 1700,4460 1700,3540 1750,3490 3670,3490 3772.68,3387.32 U1.79@3772.68,3357.87
AIN4: J4.7 U1.80 | length 3978.2
  Top Layer w10: J4.7@991.5,4980 1090,4980 1620,4450 1620,3520 1690,3450 3660.87,3450 U1.80@3752.99,3357.87
AIN5: J4.9 U1.1 | length 3966.8
  Top Layer w6: 3230,3364 3232,3362 3290,3362
  Top Layer w10: J4.9@991.5,4880 1110,4880 1540,4450 1540,3410 1593.6,3356.4 1626.4,3356.4 1634,3364 3230,3364 ; 3290,3364 3596,3364 3672.99,3287.01 U1.1@3682.13,3287.01
AIN6: J4.11 U1.2 | length 3942.5
  Top Layer w10: J4.11@991.5,4780 1110,4780 1460,4430 1460,3380 1496.8,3343.2 1501.6,3348 1579.37,3348 1586.97,3340.4 1633.03,3340.4 1640.63,3348 3542,3348 3550,3340 3580,3340 3652.68,3267.32 U1.2@3682.13,3267.32
AIN7: J4.13 U1.9 | length 3978.4
  Top Layer w10: J4.13@991.5,4680 1120,4680 1370,4430 1370,3380 1430,3320 v2(2810,3320) ; v1(2900,3190) 3500,3190 3520,3170 3570,3170 3584.62,3155.38 3587.25,3155.38 3613.1,3129.53 U1.9@3682.13,3129.53
  Bottom Layer w10: v2(2810,3320) 2805.5,3315.5 2805.5,3304.5 2810,3304.5 2835,3279.5 2835,3240.16 v1@2890,3185.16
AIN8: J4.15 U1.10 | length 4188.4
  Top Layer w10: J4.15@991.5,4580 1100,4580 1290,4390 1290,3220 1320,3190 v2(1360,3190) ; v1@1376.8,3056.8 v1@1380,3060 ; v1@1380,3056.8 2870.03,3056.8 2873.23,3060 2879.23,3054 2900.77,3054 2916,3069.23 2916,3111.44 2974.56,3170 2976.74,3172.18 3023.26,3172.18 3026.06,3169.38 3238.67,3169.38 3239.29,3170 3480,3170 3500,3150 3520,3150 3530,3140 3580,3140 3610.16,3109.84 U1.10@3682.13,3109.84
  Bottom Layer w10: v2(1360,3190) 1360,3100 1380,3080 v1(1380,3050)
D+: J6.3 R3.2 U2.3 | length 950.8
  Top Layer w10: R3.2@98.5,4400 64,4400 64,4929.04 U2.3@102.76,4967.8 154.96,5020 220,5020 289,5089 J6.3@289,5185
D-: J6.2 R4.2 U2.2 | length 748.5
  Top Layer w10: R4.2@98.5,4565 98.5,4618.5 v1(100,4620) ; v2(190,4840) 150,4880 150,4920.56 U2.2@197.24,4967.8 314.5,5085.06 J6.2@314.5,5185
  Bottom Layer w10: v1(100,4620) 150,4670 150,4800 160,4800 190,4830 v2(190,4840)
GND: C1.2 C2.2 C3.2 C4.2 C5.2 C6.1 C7.2 C8.2 C9.2 C10.1 C11.1 C12.2 C13.2 C14.2 C17.2 C18.2 C19.1 C20.1 C30.2 C31.2 C34.2 D1.2 D2.2 D3.2 J1.9 J2.2 J2.3 J4.3 J5.1 J6.5 R2.1 R5.1 R18.1 R31.1 U1.14 U1.19 U1.49 U1.61 U1.68 U2.1 U3.1 U3.4 U3.41 U4.4 U4.9 U4.V U4.V_2 | length 6090
  Top Layer w10: R2.1@161.5,4240 v1(230,4240) ; v1(450,4620) v1@451.5,4618.5 ; v1(3060,4540) 3129.96,4540 C7.2@3138.46,4548.5 C5.2@3318.59,4548.5 C6.1@3498.72,4548.5 3561.5,4548.5 3580,4530 U4.4@3660,4530 ; J2.2@3640,5180 3660,5180 3720,5240 3720,5301.5 ; J2.3@3640,5280 3660,5300 3690,5300 3691.5,5301.5 3720,5301.5 ; 3641.1,3031.1 U1.14@3682.13,3031.1 ; U4.4@3664.88,4531.61 3681.61,4531.61 U4.9@3720,4570 ; v1(3720,5340) 3720,5301.5 ; C11.1@3860,3940 v7(3920,3940) ; v1(3970,3300) 3989.21,3319.21 U1.68@3989.21,3357.87 ; v7(4060,3940) C10.1@4128.5,3940 C10.1@4140,3940 ; U1.61@4127.01,3357.87 4127.01,3387.01 4150,3410 ; J1.9@4251.5,5240 4190,5301.5 3720,5301.5 ; U3.4@4337.13,1590.47 4409.53,1590.47
  Top Layer w12: 3615.36,2930 3612.68,2932.68 U1.19@3682.13,2932.68 ; U1.49@4220,3070 4290,3070 ; U3.1@4337.13,1531.42 4338.58,1531.42 4390,1480
  Top Layer w20: v1@98.5,4681.5 R5.1@98.5,4730 ; U2.1@197.24,4900.08 269.92,4900.08 v1@270,4900 ; 238,5108 J6.5@238,5185 ; C20.1@1231.5,5310 1231.5,5258.5 1240,5250 ; C17.2@3510,2860 3540,2890 3575.36,2890 3615.36,2930 ; v5(3530,3010) 3620,3010 3641.1,3031.1 ; C30.2@4370,1370 4380,1370 v8(4430,1320) C31.2@4430,1250 ; 4390,1480 v5(4460,1410) ; 4409.53,1590.47 4460,1540 4460,1530 4600,1530 4600,1450 v9(4610,1440) ; v6(4560,2190) 4560,2140 4590,2110 R31.1@4590,2080 ; C12.2@4571.5,3110 4601.5,3080 v5@4650,3080 ; v1(4811.34,4181.34) D3.2@4811.34,4290 D2.2@4811.34,4464 D1.2@4811.34,4634
  Top Layer w25: v1(200,5070) 238,5108 ; v1(388.5,4341.5) C3.2@388.5,4400 ; C2.2@451.5,4564.97 v1@451.5,4618.5 ; v1@451.5,4621.5 C1.2@451.5,4730 ; C4.2@670,4481.18 v1(670,4570) ; v1(800,3830) C19.1@878.5,3830 ; J4.3@1000,5180 1020,5200 1130,5200 1180,5250 1240,5250 v5(1330,5250) ; J5.1@2710,5280 2760,5330 v5(2830,5330) ; R18.1@3000,2840 3090,2840 v5(3140,2790) 3260,2790 3300,2830 3370,2830 3410,2870 3490,2870 C17.2@3505,2855 ; C18.2@3360,3610 v6(3460,3610) ; 4150,3410 4170,3410 4180,3420 v5(4260,3420) ; 4290,3070 4303.5,3083.5 4343.88,3083.5 4363.5,3063.88 4363.5,3056.5 4380,3040 v5(4440,3040) ; C8.2@4440,3520 4460,3540 4460,3600 4450,3610 v1(4450,3750)
  other v1: 100,4670 279.92,4900.08
  other v3: 4149.13,1549.13 4196.38,1549.13 4243.62,1549.13 4290.87,1549.13 4149.13,1596.38 4196.38,1596.38 4243.62,1596.38 4290.87,1596.38 4149.13,1643.62 4196.38,1643.62 4243.62,1643.62 4290.87,1643.62 4149.13,1690.87 4196.38,1690.87 4243.62,1690.87 4290.87,1690.87
  other v5: 4650,3070
GPIO1_ACLK: J4.10 U1.21 U3.6 | length 6991.4
  Top Layer w6: U3.6@4337.13,1629.84 4479.84,1629.84 v2(4490,1640)
  Top Layer w10: J4.10@891.5,4880 941.5,4830 1110,4830 1500,4440 1500,3590 v1(1510,3590) ; v1(1490,3010) 1490,2770 1590,2670 v1(2490,2670) ; v1(2640,2650) 2850,2650 2910,2710 3560,2710 3650,2800 3710.87,2800 ; v1(3679.13,2770.87) 3690.87,2770.87 3690.87,2780 3710.87,2800 ; U1.21@3752.99,2842.13 3710.87,2800
  Bottom Layer w6: 4450,2760 4484,2726 4484,1670.6 4481.7,1668.3 4481.7,1648.3 v2(4490,1640)
  Bottom Layer w10: v1(1490,3010) 1510,3030 v1(1510,3590) ; v1(2490,2670) 2620,2670 v1(2640,2650) ; v1(3679.13,2770.87) 4209.13,2770.87 4220,2760 4450,2760
GPIO2_LED1: J4.16 JP5.2 U1.22 U3.7 | length 10035.5
  Top Layer w10: J4.16@891.5,4580 940,4531.5 1061.52,4531.5 1069.35,4539.32 1250,4358.67 1250,4220 1270,4200 1270,4090 ; v1(1240,4090) 1270,4090 ; v1(1270,3050) 1270,2740 1390,2620 v1(2450,2620) ; v1(1270,3160) 1270,4090 ; v1(2620,2610) 2860,2610 2932,2682 3622,2682 3640,2700 ; v1(3640,2730) 3640,2700 ; U1.22@3772.68,2842.13 3772.68,2752.68 3720,2700 3640,2700 ; v1(3820,4680) 3974,4680 JP5.2@4020,4634 ; U3.7@4337.13,1649.53 4449.53,1649.53 4449.53,1652.18 v1(4446.8,1654.9)
  Bottom Layer w10: v1(1240,4090) 2619.19,4090 2836.39,4307.2 3654.57,4307.2 3820,4472.63 v1(3820,4680) ; v1(1270,3050) v1(1270,3160) ; v1(2450,2620) 2460,2610 v1(2620,2610) ; v1(3640,2730) 3650,2740 4210,2740 4260,2690 4470,2690 4470,1676.4 4446.8,1653.2 v1(4446.8,1654.9)
GPIO3_LED2: J5.19 JP4.2 U1.27 U3.8 | length 7654.4
  Top Layer w10: v2(2480,3700) 2480,3750 2580,3850 2580,4268.5 J5.19@2691.5,4380 2691.5,4338.5 v2(2740,4290) ; v1(2530,2440) 3643.23,2440 3749.23,2546 3763.37,2546 3793.37,2576 3810.56,2576 3832.28,2597.72 ; v1(3810,2610) 3820,2610 3832.28,2597.72 ; v2(3870,4580) 3900,4550 3900,4509.36 3945.36,4464 JP4.2@4020,4464 ; U1.27@3871.1,2842.13 3871.1,2636.54 3832.28,2597.72 ; U3.8@4337.13,1669.21 4409.21,1669.21 4410,1670 v2(4410,1680) ; v2(4430,2020) 4430,2028 4414,2044 4414,2080.77 4430,2096.77 4430,2310 v1(4440,2310)
  Bottom Layer w10: v2(2480,3700) 2470,3700 2470,3276.77 2444,3250.77 2444,3219.6 2450,3213.6 2450,3110 2270,2930 2270,2470 2300,2440 v1(2530,2440) ; v2(2740,4290) 2910,4460 3240,4460 3240,4630 3320,4710 3820,4710 3824,4706 3830.77,4706 3846,4690.77 3846,4684 3870,4660 v2(3870,4580) ; v1(3810,2610) 3830,2630 3860,2630 3870,2640 4042.58,2640 4058.09,2624.5 4077.31,2624.5 4112.81,2660 4430,2660 4430,2310 v1(4440,2310) ; v2(4410,1680) 4430,1680 4450,1700 4450,1960 4450.39,1960.39 4453.2,1960.39 4453.2,1996.8 v2(4430,2020)
GPIO4_LED3: J5.17 JP3.2 U1.28 U3.27 | length 7034
  Top Layer w10: v1@2390,3700 2390,4290 2520,4420 2540,4420 2550,4430 2641.5,4430 ; v1(2590,2410) 2600,2420 3660,2420 v1(3760,2520) 3800,2560 3820,2560 3846.8,2586.8 3846.8,2589.61 3860.39,2603.2 3863.2,2603.2 3890,2630 3890,2790 3890.79,2790.79 U1.28@3890.79,2842.13 ; J5.17@2691.5,4480 2641.5,4430 ; v2(2866,4284) 2720,4430 2641.5,4430 ; v1(3934,4284) JP3.2@4020,4284 ; v1(3970,1520) 4010,1520 4080.47,1590.47 U3.27@4102.87,1590.47
  Bottom Layer w10: v1(2400,3700) 2400,3200 2410,3190 2410,3160 2246.8,2996.8 2240,2990 2240,2440 2268,2412 2588,2412 v1(2590,2410) ; v2(2866,4284) 3510,4284 3510,4283.23 3589.23,4204 3610.77,4204 3686.77,4280 3690,4280 3686.81,4283.19 3686.81,4284 v1(3934,4284) ; v1(3760,2520) 3770,2510 3770,1720 v1(3970,1520)
GPIO5: J5.15 U1.42 | length 3460
  Top Layer w6: v2(2377,3403) 2386,3394 3673.7,3394 3674.5,3393.2 3674.5,3385.5 4127.32,2932.68 U1.42@4197.87,2932.68
  Top Layer w10: v2(2330,3720) 2320,3730 2320,3960 2310,3970 2310,4310 2490,4490 2517.37,4490 2523.37,4496 2546.01,4496 2573.49,4523.48 2623.48,4523.48 2680,4580 J5.15@2691.5,4580
  Bottom Layer w6: 2376.8,3683.2 2377,3683 v2(2377,3403)
  Bottom Layer w10: v2(2330,3720) 2350,3720 2370,3700 2370,3690 2376.8,3683.2
GPIO6: J5.7 U1.43 | length 4473.3
  Top Layer w6: U1.43@4197.87,2952.36 4237.64,2952.36 4250,2940 v2(4260,2940)
  Top Layer w10: v1(2535,3606.8) v1@2531.8,3610 ; v1@2540,3610 v1@2531.8,3610 ; J5.7@2691.5,4980 2680,4980 2623.48,4923.48 2573.49,4923.48 2546.01,4896 2503.37,4896 2502.37,4895 2485,4895 2000,4410 2000,3630 2020,3610 v1@2531.8,3610
  Bottom Layer w6: 2550,3610 2550,3520 2560,3510 2560,3400 2610,3350 2810,3350 2860,3300 2860,3270 2950,3180 3560,3180 3570,3170 3570,3152.61 3642,3080.61 3642,3058 3760,2940 v2(4260,2940)
GPIO7: J5.5 U1.44 | length 4750.9
  Top Layer w6: v1(1940,3420) 1990,3420 2000,3430 2630,3430 v2(2640,3420) ; U1.44@4197.87,2972.05 4277.95,2972.05 v2(4290,2960)
  Top Layer w10: v1(1910,3620) 1910,3760 1930,3780 1930,4450 2480,5000 2550.01,5000 2573.49,5023.48 2603.48,5023.48 2660,5080 J5.5@2691.5,5080
  Bottom Layer w6: v2@2650,3420 2680,3390 2770,3390 2798,3362 2814.97,3362 2872,3304.97 2872,3288 2960,3200 3570,3200 3570,3186.97 3654,3102.97 3654,3062.97 3746.97,2970 4240.3,2970 4241.3,2971 4258.7,2971 4259.7,2970 4280,2970 v2(4290,2960)
  Bottom Layer w10: v1(1910,3620) 1910,3450 v1(1940,3420)
GPIO8: J4.17 U1.45 | length 4459.8
  Top Layer w10: J4.17@991.5,4480 1030,4480 1210,4300 1210,3940 1230,3920 v2(1230,3720) ; v2(1810,3550) v1(2710,3550) ; U1.45@4197.87,2991.73 4201.39,2995.25 4297.56,2995.25 4301.08,2991.73 4311.73,2991.73 4320,3000 v1(4320,2994.4)
  Bottom Layer w6: 3033.6,3226.4 3040,3220 3553.94,3220 3561.94,3212 3574.97,3212 3666,3120.97 3666,3084 3763.6,2986.4 4269.49,2986.4
  Bottom Layer w10: v2(1230,3720) 1230,3690 1240,3680 1350,3680 1364,3666 1694,3666 v2(1810,3550) ; v1(2710,3550) 2710.14,3550 3030.14,3230 3030.14,3229.86 3033.6,3226.4 ; 4269.49,2986.4 4278.34,2995.25 4315.25,2995.25 4320,3000 v1(4320,2994.4)
GPIO9: J4.19 U1.48 | length 4009.9
  Top Layer w6: v2(4040,3070) 4059,3051 4080.9,3051 4081.11,3050.79 U1.48@4197.87,3050.79
  Top Layer w10: J4.19@991.5,4380 1100,4271.5 v1(1100,3970)
  Bottom Layer w6: 2675.08,3666.4 2697,3644.48 2697,3633 2700.94,3633 2767.2,3566.74 2767.2,3546.8 3050,3264 3573.88,3264 3704,3133.88 3704,3112.97 3786.97,3030 3900.63,3030 3940.63,3070 v2(4040,3070)
  Bottom Layer w10: v1(1100,3970) 1137.19,3970 1150.39,3983.2 1169.61,3983.2 1183.2,3969.61 1183.2,3966.8 1260,3890 1350,3890 1430,3810 2350,3810 2410,3750 2580,3750 2663.6,3666.4 2675.08,3666.4
GPIO10: J5.20 U1.51 | length 2768
  Top Layer w6: v2(4090,3090) 4140,3090 4159.84,3109.84 U1.51@4197.87,3109.84
  Top Layer w10: v2(2470,3780) 2440,3780 2420,3800 2420,4260 2540,4380 J5.20@2591.5,4380
  Bottom Layer w6: 2640,3720 2641.28,3720 2689.08,3672.2 2689.08,3670.92 3084,3276 3578.85,3276 3744.85,3110 4070,3110 v2(4090,3090)
  Bottom Layer w10: v2(2470,3780) 2470,3770 2590,3770 2640,3720
GPIO11: J5.18 U1.52 | length 2915.6
  Top Layer w6: v2(4050,3140) 4060,3140 4070.47,3129.53 U1.52@4197.87,3129.53
  Top Layer w10: v1(2360,3860) 2360,4220 2350,4230 2350,4300 2530,4480 J5.18@2591.5,4480
  Bottom Layer w6: 2656.8,3733.2 3102,3288 3584,3288 3750,3122 3992,3122 4010,3140 v2(4050,3140)
  Bottom Layer w10: v1(2360,3860) 2390,3830 2440,3830 2467,3803 2479.53,3803 2492.53,3790 2600,3790 2656.8,3733.2
GPIO12: J5.16 U1.53 | length 3123.8
  Top Layer w10: v1(2290,3890) 2300,3890 2300,3900 2280,3920 2280,4000 2270,4010 2270,4320 2530,4580 J5.16@2591.5,4580 ; v1(4100,3170) 4100,3150 4100.79,3149.21 4106.4,3149.21 4120.39,3163.2 4139.61,3163.2 4153.6,3149.21 U1.53@4197.87,3149.21
  Bottom Layer w10: v1(2290,3890) 2470,3890 2550,3810 2610,3810 2670,3750 2710,3750 3150,3310 3330,3310 3330.4,3309.6 3593.74,3309.6 3733.34,3170 3973.93,3170 3978.93,3165 4041.07,3165 4046.07,3170 v1(4100,3170)
GPIO13: J5.14 U1.72 | length 2969.7
  Top Layer w10: J5.14@2591.5,4680 2530,4680 2200,4350 2200,3780 2306.8,3673.2 3618.62,3673.2 3741.82,3550 3750,3550 3910,3390
I2C_SCL: J4.18 R21.2 U1.47 U3.11 | length 6166.7
  Top Layer w6: v2@4072.2,3031.1 U1.47@4197.87,3031.1 ; 4258.9,3031.1 4291.1,3031.1 4310,3050 v2(4320,3050) ; U3.11@4308.6,1737.13 4308.6,1758.6 4320,1770 4320,1840 4384,1904 4384,2336 v1(4380,2340)
  Top Layer w10: R21.2@878.5,4130 840,4130 820,4150 820,4390 891.5,4461.5 J4.18@891.5,4480 941.5,4430 1030,4430 1110,4350 1110,4330 1150,4290 1150,4100 1160,4090 1160,3960 1170,3950 1170,3880 v2(1190,3860) ; v2@4071.1,3031.1 v2(4072.2,3030) ; U1.47@4197.87,3031.1 4258.9,3031.1 ; v1(4350,2540) v1(4350,2820)
  Bottom Layer w6: 2645.47,3653.2 2645.47,3651.5 2675.97,3621 2695.97,3621 2755.2,3561.77 2755.2,3541.77 3044.97,3252 3568.91,3252 3692,3128.91 3692,3108 3787.6,3012.4 3900,3012.4 3917.6,3030 v2(4072.2,3030) ; v2(4320,3050) 4350,3020 4360,3020 4380,3000
  Bottom Layer w10: v2(1190,3860) 1260,3790 2320,3790 2380,3730 2568.67,3730 2645.47,3653.2 ; v1(4350,2540) 4382,2508 4382,2428.76 4374,2420.77 4374,2399.23 4382,2391.24 4382,2382 4390,2373.99 4390,2340 v1(4380,2340) ; v1(4350,2820) 4380,2850 4380,3000
I2C_SDA: J4.20 R22.2 U1.46 U3.10 | length 6000.3
  Top Layer w6: 2120,3630 2524.26,3630 2525.06,3630.8 2544.94,3630.8 2545.74,3630 2630,3630 2660,3600 v2(2670,3600) ; v2(4110,3010) 4140,3010 4141.42,3011.42 U1.46@4197.87,3011.42 ; U3.10@4337.13,1708.58 4380,1751.46 4380,1870 4396,1886 4396,2246 4400,2250 4400,2276.4 4406.8,2283.2 4406.8,2290
  Top Layer w10: v2(860,3920) 878.5,3938.5 R22.2@878.5,3980 ; J4.20@891.5,4380 1001.5,4270 1020,4270 1040,4250 1040,4000 v1(1057.19,3982.81) ; v1(2080,3670) 2120,3630 ; U1.46@4197.87,3011.42 4198.04,3011.25 4300.08,3011.25 4309.23,3020.4 4323.03,3020.4 4325.83,3023.2 4329.61,3023.2 4342.81,3010 4400,3010 v1(4400,2620) ; v1(4400,2410) v1@4406.8,2410 ; 4406.8,2290 v1@4406.8,2410 ; v1@4406.8,2410 4410,2410 4406.8,2413.2 v1@4406.8,2410
  Bottom Layer w6: v2(2670,3600) 2700,3600 2743.2,3556.8 2740,3553.6 2740,3540 3040,3240 3563.94,3240 3680,3123.94 3680,3090 3770,3000 3810,3000 ; 3809.6,3000.4 3960,3000.4 3968.6,3009 4109,3009 v2(4110,3010)
  Bottom Layer w10: v2(860,3920) 1030,3920 1057.19,3947.19 1057.19,3980 1070,3967.19 1070,3900 1227,3743 1253,3743 1300,3696 1482.27,3696 1488.67,3689.6 1799.07,3689.6 1818.67,3670 v1(2080,3670) ; v1(4400,2410) 4410,2400 4410,2610 v1(4400,2620)
KSI0: J3.5 R10.1 U1.29 U3.29 | length 8610.9
  Top Layer w6: v2(3740,1230) 3790,1280 3831.66,1280 4077.14,1525.48 4077.14,1544.53 4082.61,1550 4101.77,1550 U3.29@4102.87,1551.1
  Top Layer w10: R10.1@920,2368.5 881.43,2329.93 881.43,2318.57 ; v1(930,2310) 890,2310 881.43,2318.57 ; v1(1980,2320) 3880,2320 3910.47,2350.47 U1.29@3910.47,2842.13 ; v2(3740,740) 2970,740 2960,730 1640,730 974.72,1395.28 J3.5@974.72,1924 974.72,1995.28 881.43,2088.57 881.43,2318.57
  Bottom Layer w10: v1(930,2310) 940,2320 v1(1980,2320) ; v2(3740,740) v2(3740,1230)
KSI1: J3.8 R11.1 U1.30 U3.30 | length 7957
  Top Layer w10: R11.1@1018.57,2367.2 1018.57,2298.57 1010,2290 ; v1(1050,2290) 1010,2290 ; v1(2020,2290) 3890,2290 3930.16,2330.16 U1.30@3930.16,2842.13 ; v1(3440,840) 2120,840 2110,830 1750,830 1092.83,1487.17 J3.8@1092.83,1924 1092.83,2127.17 1010,2210 1010,2290 ; v1(3470,900) 3471.46,900 U3.30@4102.87,1531.42
  Bottom Layer w10: v1(1050,2290) v1(2020,2290) ; v1(3440,840) 3440,870 v1(3470,900)
KSI2: J3.9 R12.1 U1.31 U3.31 | length 7902.8
  Top Layer w10: v2(1110,2255.71) 1155.71,2210 ; R12.1@1155.71,2367.2 1155.71,2210 ; v1(2100,2260) 2110,2260 2136.23,2233.77 2139.17,2233.77 2164.94,2208 3116.75,2208 3156.75,2248 3908,2248 3949.84,2289.84 U1.31@3949.84,2842.13 ; U3.31@4131.39,1502.87 3498.52,870 1780,870 1132.2,1517.8 J3.9@1132.2,1924 1132.2,2152.2 1155.71,2175.71 1155.71,2210
  Bottom Layer w10: v2(1110,2255.71) 1185.71,2255.71 1190,2260 v1(2100,2260)
KSI3: J3.11 R13.1 U1.32 U3.32 | length 7579.4
  Top Layer w10: R13.1@1292.86,2367.2 1292.86,2172.86 ; v1(1372,2222) 1360,2210 1330,2210 1292.86,2172.86 ; v1(2087.77,2217.77) 2132.54,2217.77 2158.31,2192 3123.37,2192 3163.37,2232 3921.06,2232 3969.53,2280.47 U1.32@3969.53,2842.13 ; v1(3490,990) 3430,990 3420,980 1780,980 1210.94,1549.06 J3.11@1210.94,1924 1210.94,2090.94 1292.86,2172.86 ; v1(3660,990) 3655.67,990 3652.84,992.84 3660,992.84 4145.11,1477.94 4147.94,1477.94 4151.08,1481.08 U3.32@4151.08,1502.87
  Bottom Layer w10: v1(1372,2222) 2083.54,2222 v1(2087.77,2217.77) ; v1(3490,990) v1(3660,990)
KSI4: J3.18 R14.1 U1.33 U3.33 | length 6869.1
  Top Layer w10: R14.1@1430,2367.2 1430,2180 ; v1(1521.77,2191.77) 1520,2190 1440,2190 1430,2180 ; v1(2121.77,2191.77) 2120,2190 2134,2176 3130,2176 3170,2216 3936,2216 3989.21,2269.21 U1.33@3989.21,2842.13 ; v1(3830,1350) 3770,1350 3750,1330 1790,1330 1486.54,1633.46 J3.18@1486.54,1924 1486.54,2123.46 1430,2180 ; v1(4050,1340) 4170.77,1460.77 U3.33@4170.77,1502.87
  Bottom Layer w10: v1(1521.77,2191.77) 1659.14,2191.77 1663.37,2196 2019.23,2196 2029.23,2206 2050.77,2206 2065,2191.77 v1(2121.77,2191.77) ; v1(3830,1350) 3840,1340 v1(4050,1340)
